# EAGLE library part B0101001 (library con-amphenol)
AMPHENOL CONNECTOR
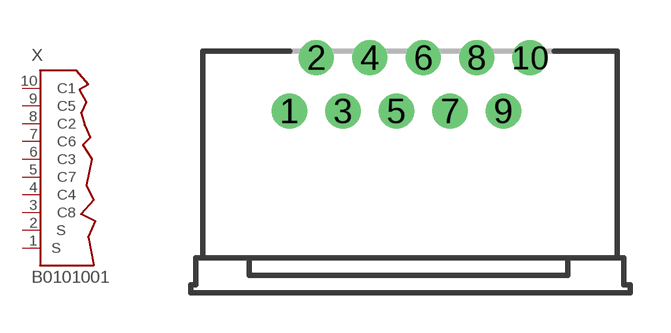
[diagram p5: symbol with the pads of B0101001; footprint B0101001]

Designator prefix X

## B0101001 (MF: AMPHENOL; MPN: C00710B0101001; OC_FARNELL: unknown; OC_NEWARK: 07C1376)  [B0101001]
1  S1  pas
2  S2  pas
3  C8  pas
4  C4  pas
5  C7  pas
6  C3  pas
7  C6  pas
8  C2  pas
9  C5  pas
10  C1  pas

## Footprint B0101001 (pad centres in mm)
AMPHENOL CONNECTOR
drill 0.813 round: 1 -4.5,-1; 2 -3.5,1; 3 -2.5,-1; 4 -1.5,1; 5 -0.5,-1; 6 0.5,1; 7 1.5,-1; 8 2.5,1; 9 3.5,-1; 10 4.5,1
